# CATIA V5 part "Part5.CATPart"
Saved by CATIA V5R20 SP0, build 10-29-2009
Part number: 角
Bounding box of the stored display mesh (mm): x -4 to 4, y -30.984 to -16.984, z -7 to -4
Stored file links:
  D:\CATIA Data\Part5.CATPart
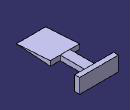
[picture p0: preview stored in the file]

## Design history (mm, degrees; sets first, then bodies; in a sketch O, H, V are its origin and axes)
Body1 (main body)
  Sketch1 on yz-plane, origin (0, 0, 0), H (0, 1, 0), V (0, 0, 1)
    line L1 (-23.984, -5) -> (-17.984, -5)
    line L2 (-17.984, -5) -> (-17.984, -6)
    line L3 (-17.984, -6) -> (-23.984, -6)
    line L4 (-23.984, -6) -> (-23.984, -5)
    length L4 = 1
    length L1 = 6
    distance H L1 = 5
    distance L2 V = 17.984
    horizontal: L1 H, L3 H
    vertical: L2 V, L4 V
  Pad1: profile Sketch1, direction (1, 0, 0), length 1, mirrored extent
  Plane1: type Offset, RefPlane end face of Pad1, Offset 1
  Sketch2 on Plane1, origin (0, 0, 0), H (0, -1, 0), V (0, 0, 1)
    point P1 (30.984, -5.5)
    line L1 (30.984, -5.5) -> (23.984, -5)
    point P2 (23.984, -5)
    line L2 (23.984, -5) -> (23.984, -6)
    point P3 (23.984, -6)
    line L3 (23.984, -6) -> (30.984, -5.5)
    reference projected line E1 (17.984, -5) -> (23.984, -5) from edge [start face of Pad1 | face of Pad1 from Sketch1.L1]
    reference projected line E2 (23.984, -5) -> (23.984, -6) from edge [start face of Pad1 | face of Pad1 from Sketch1.L4]
    reference projected line E3 (23.984, -6) -> (17.984, -6) from edge [start face of Pad1 | face of Pad1 from Sketch1.L3]
    reference projected line E4 (17.984, -5) -> (23.984, -5) from edge [start face of Pad1 | face of Pad1 from Sketch1.L1]
    distance P1 L2 = 7
    distance P1 E4 = 0.5
    vertical: L2 V
    coincidence: P2 E1, L2 E2, P3 E3
  Pad2: profile Sketch2, direction (-1, 0, 0), length 3, mirrored extent
  Sketch3 on face of Pad1 from Sketch1.L2, origin (0, -17.984, 0), H (-1, 0, 0), V (0, 0, 1)
    line L1 (-4, -4) -> (4, -4)
    line L2 (4, -4) -> (4, -7)
    line L3 (4, -7) -> (-4, -7)
    line L4 (-4, -7) -> (-4, -4)
    reference projected line E1 (1, -5) -> (-1, -5) from edge [face of Pad1 from Sketch1.L1 | face of Pad1 from Sketch1.L2]
    reference projected line E2 (-1, -6) -> (-1, -5) from edge [face of Pad1 from Sketch1.L2 | end face of Pad1]
    length L1 = 8
    length L4 = 3
    distance L1 E1 = 1
    distance L2 E2 = 5
    horizontal: L1 H, L3 H
    vertical: L2 V, L4 V
  Pad3: profile Sketch3, direction (0, 1, 0), length 1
